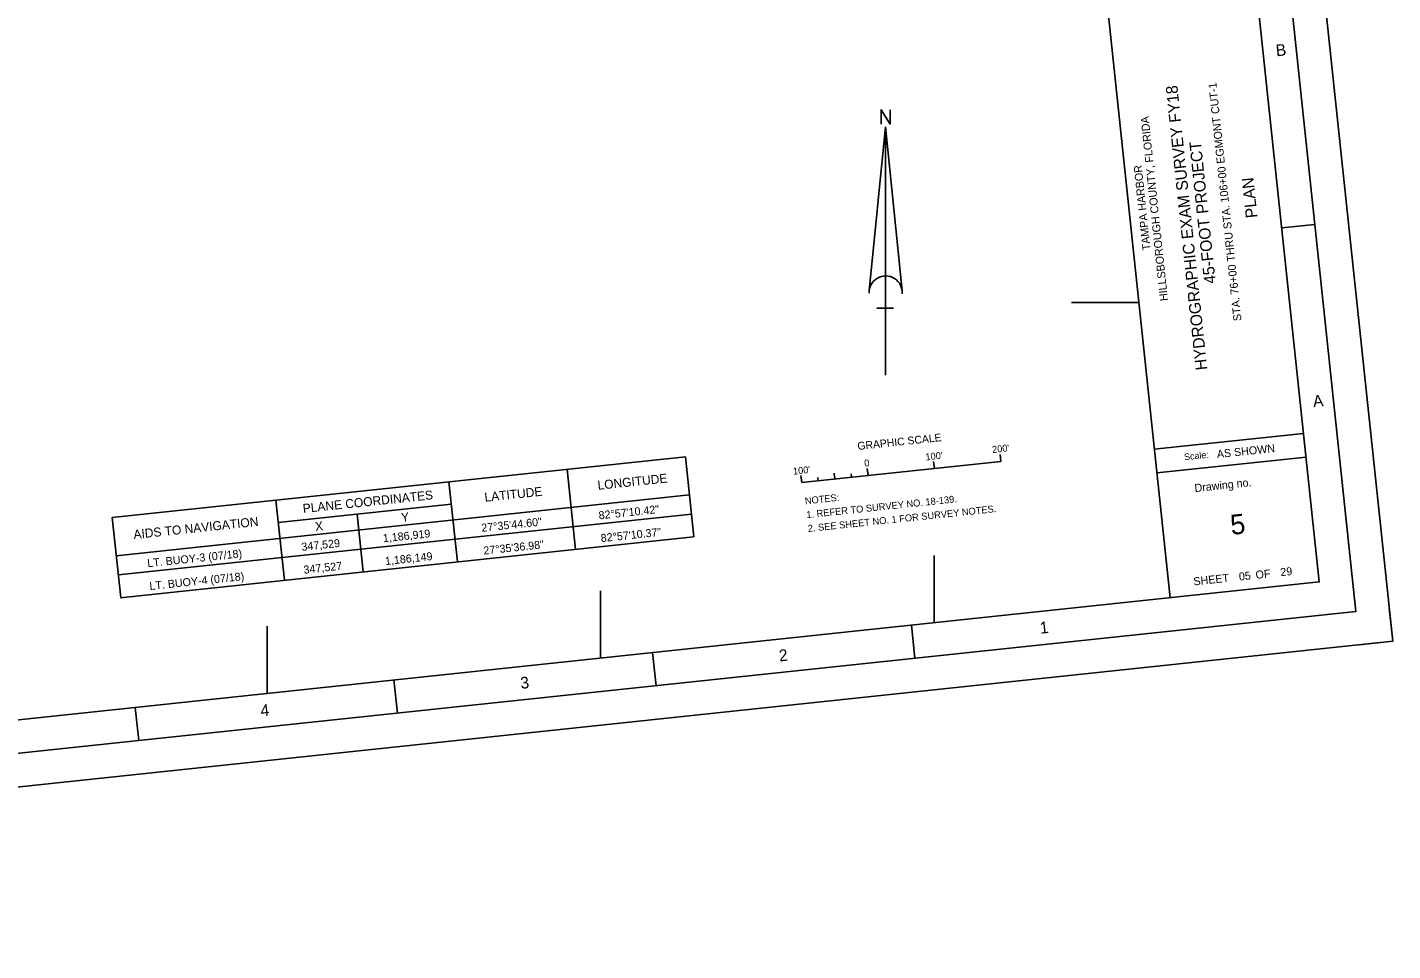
# Model space of a CAD drawing. Extents: x 344453 to 349187, y 1184529 to 1188374.
# Drawn here: x 347141 to 349187, y 1184529 to 1185912 of the extents above; entities that cross this region are included whole.
import ezdxf

# ---------------------------------------------------------------- set-up
doc = ezdxf.new("R2010")
doc.units = 0
for name, color, linetype in [('G-ANNO-NPLT', 7, 'Continuous'), ('G-ANNO-TEXT-DRWG', 7, 'Continuous'), ('G-ANNO-TEXT-PROJ', 7, 'Continuous'), ('G-ANNO-TEXT-TTLB', 7, 'Continuous'), ('G-ANNO-TTLB', 7, 'Continuous'), ('V-ANNO-NOTE', 7, 'Continuous'), ('V-ANNO-SCHD', 7, 'Continuous'), ('V-ANNO-SYMB', 7, 'Continuous'), ('V-TOPO-COOR-STAT', 7, 'Continuous')]:
    doc.layers.add(name, color=color, linetype=linetype)

msp = doc.modelspace()

# ---------------------------------------------------------------- linework, layer by layer
at = {"layer": 'G-ANNO-NPLT'}
msp.add_lwpolyline([(344453.5, 1187909.7), (348828.9, 1188373.5), (349187.3, 1184992.5), (344811.8, 1184528.7)], close=True, dxfattribs=at)
msp.add_lwpolyline([(349182, 1185042.2), (349187.3, 1184992.5), (349137.6, 1184987.2)], dxfattribs=at)
at = {"layer": 'G-ANNO-TTLB'}
for p, q in [((348516.3, 1188239.8), (348853.6, 1185057.7)), ((349070.8, 1185617), (349021.1, 1185611.7)), ((348830, 1185280.2), (349053.7, 1185303.9)), ((348833.7, 1185244.7), (349057.5, 1185268.4)), ((348471, 1184966.9), (348465.8, 1185016.6)), ((348083.2, 1184925.7), (348077.9, 1184975.5)), ((347695.4, 1184884.6), (347690.1, 1184934.4)), ((347307.6, 1184843.5), (347302.3, 1184893.2))]:
    msp.add_line(p, q, dxfattribs=at)
for points in [[(344856.3, 1184583.7), (349132.3, 1185036.9), (348784.5, 1188318.5), (344508.5, 1187865.3)], [(348740, 1188263.6), (344638, 1187828.7), (344975.3, 1184646.6), (349077.3, 1185081.4)]]:
    msp.add_lwpolyline(points, close=True, dxfattribs=at)
at = {"layer": 'V-ANNO-NOTE'}
for p, q in [((348599.8, 1185262), (348598.7, 1185272.4)), ((348301.4, 1185230.4), (348599.8, 1185262)), ((348400.9, 1185240.9), (348399.8, 1185251.3)), ((348400.9, 1185240.9), (348399.8, 1185251.3)), ((348500.3, 1185251.5), (348499.2, 1185261.9)), ((348301.4, 1185230.4), (348300.3, 1185240.8)), ((348326.3, 1185233), (348325.8, 1185237.8)), ((348351.2, 1185235.7), (348350.3, 1185244.1)), ((348376, 1185238.3), (348375.5, 1185243.1)), ((348400.9, 1185240.9), (348400.4, 1185245.9))]:
    msp.add_line(p, q, dxfattribs=at)
at = {"layer": 'V-ANNO-SCHD'}
for p, q in [((347268, 1185178), (348127.2, 1185269)), ((348140, 1185148.8), (348127.2, 1185269)), ((347949.9, 1185250.2), (347962.6, 1185130)), ((347772.6, 1185231.4), (347785.3, 1185111.2)), ((347274.1, 1185120.6), (348133.3, 1185211.6)), ((347513.3, 1185204), (347526, 1185083.8)), ((347516.9, 1185170.5), (347776.1, 1185198)), ((347268, 1185178), (347280.8, 1185057.8)), ((347277.2, 1185091.8), (348136.4, 1185182.9)), ((347635.1, 1185183), (347644.3, 1185096.3)), ((347280.3, 1185057.7), (348139.5, 1185148.8))]:
    msp.add_line(p, q, dxfattribs=at)
at = {"layer": 'V-ANNO-SYMB'}
for p, q in [((348402.6, 1185517.6), (348427.3, 1185763.3)), ((348427.3, 1185391), (348427.3, 1185763.3)), ((348452, 1185517.6), (348427.3, 1185763.3)), ((348439.1, 1185491.5), (348414.3, 1185491.5))]:
    msp.add_line(p, q, dxfattribs=at)
msp.add_lwpolyline([(348420.5, 1185767.3), (348420.5, 1185789), (348434, 1185767.3), (348434, 1185789)], dxfattribs=at)
msp.add_arc((348427.3, 1185515.1), 24.8, 355.2984, 182.0673, dxfattribs=at)
at = {"layer": 'V-TOPO-COOR-STAT'}
for p, q in [((348706.1, 1185500), (348806.7, 1185500)), ((348500, 1185020.2), (348500, 1185120.8)), ((348000, 1184967.2), (348000, 1185067.8)), ((347500, 1184914.2), (347500, 1185014.8))]:
    msp.add_line(p, q, dxfattribs=at)

# ---------------------------------------------------------------- texts
at = {"layer": 'G-ANNO-TEXT-DRWG'}
for s, height, rotation, p in [('STA. 76+00 THRU STA. 106+00 EGMONT CUT-1', 12, 96.0506, (348960.8, 1185472.8)), ('PLAN', 17.5, 96.0506, (348984.8, 1185627.5)), ('5', 30, 6.0506, (348945.5, 1185151.7)), (' 05          29', 12, 6.0506, (348953, 1185082.8))]:
    msp.add_text(s, height=height, rotation=rotation, dxfattribs=at).set_placement(p)
at = {"layer": 'G-ANNO-TEXT-PROJ'}
for s, height, p in [('HYDROGRAPHIC EXAM SURVEY FY18', 17.5, (348909.6, 1185399.5)), ('HILLSBOROUGH COUNTY, FLORIDA', 12, (348850.6, 1185502.9)), ('45-FOOT PROJECT', 17.5, (348922.3, 1185529.1)), ('TAMPA HARBOR', 12, (348824.5, 1185578.9))]:
    msp.add_text(s, height=height, rotation=96.0506, dxfattribs=at).set_placement(p)
at = {"layer": 'G-ANNO-TEXT-TTLB'}
for s, height, p in [('Scale:', 10, (348875.1, 1185263.5)), ('AS SHOWN', 12, (348924.4, 1185266.8)), ('Drawing no.', 12, (348890.9, 1185215.9)), ('SHEET         OF', 12, (348889.3, 1185076))]:
    msp.add_text(s, height=height, rotation=6.0506, dxfattribs=at).set_placement(p)
at = {"layer": 'G-ANNO-TTLB'}
for s, p in [('B', (349013, 1185868.9)), ('A', (349068.7, 1185343.1)), ('1', (348659.3, 1185003.6)), ('2', (348268.3, 1184962.1)), ('3', (347880.7, 1184921)), ('4', (347491.1, 1184879.7))]:
    msp.add_text(s, height=17.5, rotation=6.0506, dxfattribs=at).set_placement(p)
at = {"layer": 'V-ANNO-NOTE'}
for s, height, p in [('GRAPHIC SCALE', 11.666, (348385.6, 1185279)), ("100'", 10.42, (348487.4, 1185263.3)), ("200'", 10.42, (348587.3, 1185274.4)), ("100'", 10.42, (348288.9, 1185241.9)), ('0', 10.4, (348395.8, 1185253.9)), ('NOTES:', 10.42, (348306.7, 1185197.5)), ('1. REFER TO SURVEY NO. 18-139.', 10.416, (348308.9, 1185176.8)), ('2. SEE SHEET NO. 1 FOR SURVEY NOTES.', 10.416, (348311.1, 1185156.1))]:
    msp.add_text(s, height=height, rotation=6.0506, dxfattribs=at).set_placement(p)
at = {"layer": 'V-ANNO-SCHD'}
for s, height, p in [('LONGITUDE', 13.47, (347996.2, 1185219.3)), ('PLANE COORDINATES', 13.471, (347554.3, 1185184.6)), ('LATITUDE', 13.47, (347826.7, 1185201.4)), ('Y', 13.5, (347701.7, 1185171.2)), ('AIDS TO NAVIGATION', 13.471, (347300.5, 1185145.6)), ('X', 13.5, (347572.7, 1185157.5))]:
    msp.add_text(s, height=height, rotation=6.0507, dxfattribs=at).set_placement(p)
at = {"layer": 'V-ANNO-SYMB'}
for s, p in [('82%%D57\'10.42"', (347997.7, 1185175)), ('27%%D35\'44.60"', (347821.9, 1185156.3)), ('347,529', (347552.2, 1185127.8)), ('1,186,919', (347674.3, 1185140.7)), ('82%%D57\'10.37"', (348000.9, 1185140.9)), ('LT. BUOY-3 (07/18)', (347321.2, 1185103.3)), ('1,186,149', (347677.5, 1185106.6)), ('27%%D35\'36.98"', (347825, 1185122.2)), ('347,527', (347555.4, 1185093.6)), ('LT. BUOY-4 (07/18)', (347324.4, 1185069.1))]:
    msp.add_text(s, height=12, rotation=6.0506, dxfattribs=at).set_placement(p)

doc.saveas('drawing.dxf')
